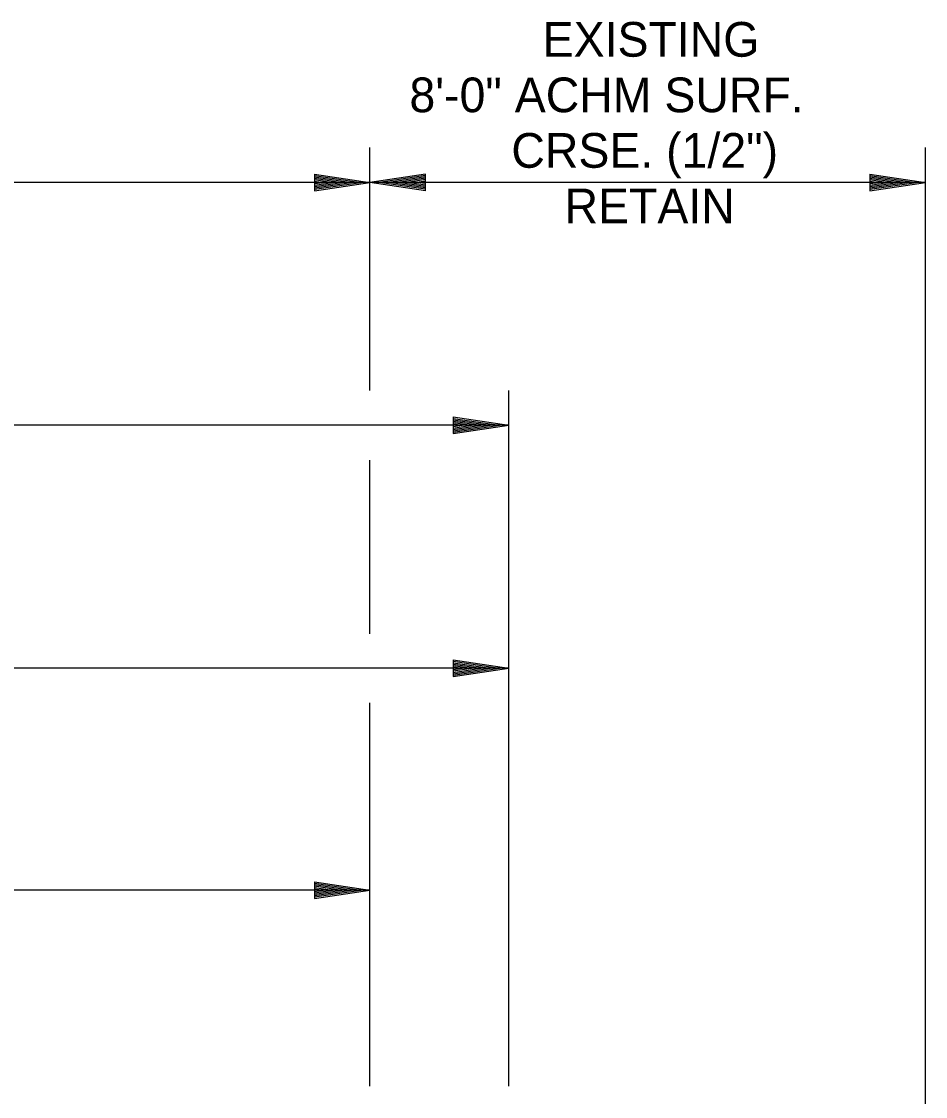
# Model space of a CAD drawing. Extents: x 60325 to 61047, y 53669 to 53767.
# Drawn here: x 60603.53 to 60616.55, y 53740.42 to 53755.91 of the extents above; entities that cross this region are included whole.
import ezdxf

# ---------------------------------------------------------------- set-up
doc = ezdxf.new("R2010")
doc.units = 0
doc.layers.add('R_Border', color=7, linetype='Continuous')
doc.layers.add('R_Border Prem', color=7, linetype='Continuous')

msp = doc.modelspace()

# ---------------------------------------------------------------- linework, layer by layer
at = {"layer": 'R_Border'}
for p, q in [((60608.545, 53740.57), (60608.545, 53744.102)), ((60607.745, 53743.516), (60608.545, 53743.396)), ((60607.745, 53743.516), (60607.745, 53743.276)), ((60608.545, 53743.396), (60580.545, 53743.396)), ((60607.745, 53743.496), (60608.412, 53743.396)), ((60607.745, 53743.476), (60608.274, 53743.396)), ((60607.745, 53743.456), (60608.141, 53743.396)), ((60607.745, 53743.435), (60608.005, 53743.396)), ((60607.745, 53743.415), (60607.872, 53743.396)), ((60607.745, 53743.276), (60608.545, 53743.396)), ((60607.745, 53743.357), (60608.005, 53743.396)), ((60607.745, 53743.317), (60608.274, 53743.396)), ((60607.745, 53743.296), (60608.412, 53743.396)), ((60607.745, 53743.337), (60608.141, 53743.396)), ((60607.745, 53743.377), (60607.872, 53743.396))]:
    msp.add_line(p, q, dxfattribs=at)
at = {"layer": 'R_Border Prem'}
for p, q in [((60608.545, 53750.591), (60608.545, 53754.091)), ((60616.545, 53740.841), (60616.545, 53754.091)), ((60608.545, 53753.591), (60534.545, 53753.591)), ((60607.745, 53753.711), (60608.545, 53753.591)), ((60607.745, 53753.711), (60607.745, 53753.471)), ((60607.745, 53753.691), (60608.412, 53753.591)), ((60607.745, 53753.671), (60608.274, 53753.591)), ((60607.745, 53753.651), (60608.141, 53753.591)), ((60607.745, 53753.63), (60608.005, 53753.591)), ((60607.745, 53753.61), (60607.872, 53753.591)), ((60607.745, 53753.471), (60608.545, 53753.591)), ((60607.745, 53753.552), (60608.005, 53753.591)), ((60607.745, 53753.512), (60608.274, 53753.591)), ((60607.745, 53753.491), (60608.412, 53753.591)), ((60607.745, 53753.532), (60608.141, 53753.591)), ((60607.745, 53753.572), (60607.872, 53753.591)), ((60609.345, 53753.711), (60608.545, 53753.591)), ((60616.545, 53753.591), (60608.545, 53753.591)), ((60609.345, 53753.471), (60608.545, 53753.591)), ((60609.345, 53753.691), (60608.679, 53753.591)), ((60609.345, 53753.491), (60608.679, 53753.591)), ((60609.345, 53753.671), (60608.816, 53753.591)), ((60609.345, 53753.512), (60608.816, 53753.591)), ((60609.345, 53753.651), (60608.95, 53753.591)), ((60609.345, 53753.532), (60608.95, 53753.591)), ((60609.345, 53753.63), (60609.085, 53753.591)), ((60609.345, 53753.552), (60609.085, 53753.591)), ((60609.345, 53753.61), (60609.219, 53753.591)), ((60609.345, 53753.572), (60609.219, 53753.591)), ((60609.345, 53753.471), (60609.345, 53753.711)), ((60615.745, 53753.711), (60616.545, 53753.591)), ((60615.745, 53753.711), (60615.745, 53753.471)), ((60615.745, 53753.691), (60616.412, 53753.591)), ((60615.745, 53753.671), (60616.274, 53753.591)), ((60615.745, 53753.651), (60616.141, 53753.591)), ((60615.745, 53753.63), (60616.005, 53753.591)), ((60615.745, 53753.61), (60615.872, 53753.591)), ((60615.745, 53753.471), (60616.545, 53753.591)), ((60615.745, 53753.552), (60616.005, 53753.591)), ((60615.745, 53753.512), (60616.274, 53753.591)), ((60615.745, 53753.491), (60616.412, 53753.591)), ((60615.745, 53753.532), (60616.141, 53753.591)), ((60615.745, 53753.572), (60615.872, 53753.591)), ((60610.545, 53740.57), (60610.545, 53750.591)), ((60609.745, 53750.211), (60610.545, 53750.091)), ((60609.745, 53750.211), (60609.745, 53749.971)), ((60609.745, 53750.191), (60610.412, 53750.091)), ((60609.745, 53750.171), (60610.274, 53750.091)), ((60610.545, 53750.091), (60532.545, 53750.091)), ((60609.745, 53750.151), (60610.141, 53750.091)), ((60609.745, 53750.13), (60610.005, 53750.091)), ((60609.745, 53750.11), (60609.872, 53750.091)), ((60609.745, 53749.971), (60610.545, 53750.091)), ((60609.745, 53750.052), (60610.005, 53750.091)), ((60609.745, 53750.012), (60610.274, 53750.091)), ((60609.745, 53749.991), (60610.412, 53750.091)), ((60609.745, 53750.032), (60610.141, 53750.091)), ((60609.745, 53750.072), (60609.872, 53750.091)), ((60608.545, 53747.089), (60608.545, 53749.591)), ((60609.745, 53746.711), (60610.545, 53746.591)), ((60609.745, 53746.711), (60609.745, 53746.471)), ((60609.745, 53746.691), (60610.412, 53746.591)), ((60609.745, 53746.671), (60610.274, 53746.591)), ((60609.745, 53746.651), (60610.141, 53746.591)), ((60609.745, 53746.63), (60610.005, 53746.591)), ((60609.745, 53746.61), (60609.872, 53746.591)), ((60610.545, 53746.591), (60532.545, 53746.591)), ((60609.745, 53746.471), (60610.545, 53746.591)), ((60609.745, 53746.552), (60610.005, 53746.591)), ((60609.745, 53746.512), (60610.274, 53746.591)), ((60609.745, 53746.491), (60610.412, 53746.591)), ((60609.745, 53746.532), (60610.141, 53746.591)), ((60609.745, 53746.572), (60609.872, 53746.591)), ((60608.545, 53744.102), (60608.545, 53746.091)), ((60616.545, 53735.251), (60616.545, 53740.841))]:
    msp.add_line(p, q, dxfattribs=at)

# ---------------------------------------------------------------- texts
for s, p in [('EXISTING', (60611.032, 53755.401)), ('8\'-0" ACHM SURF.', (60609.113, 53754.601)), ('CRSE. (1/2")', (60610.581, 53753.801)), ('RETAIN', (60611.347, 53753.001))]:
    msp.add_text(s, height=0.5, dxfattribs=at).set_placement(p)

doc.saveas('drawing.dxf')
